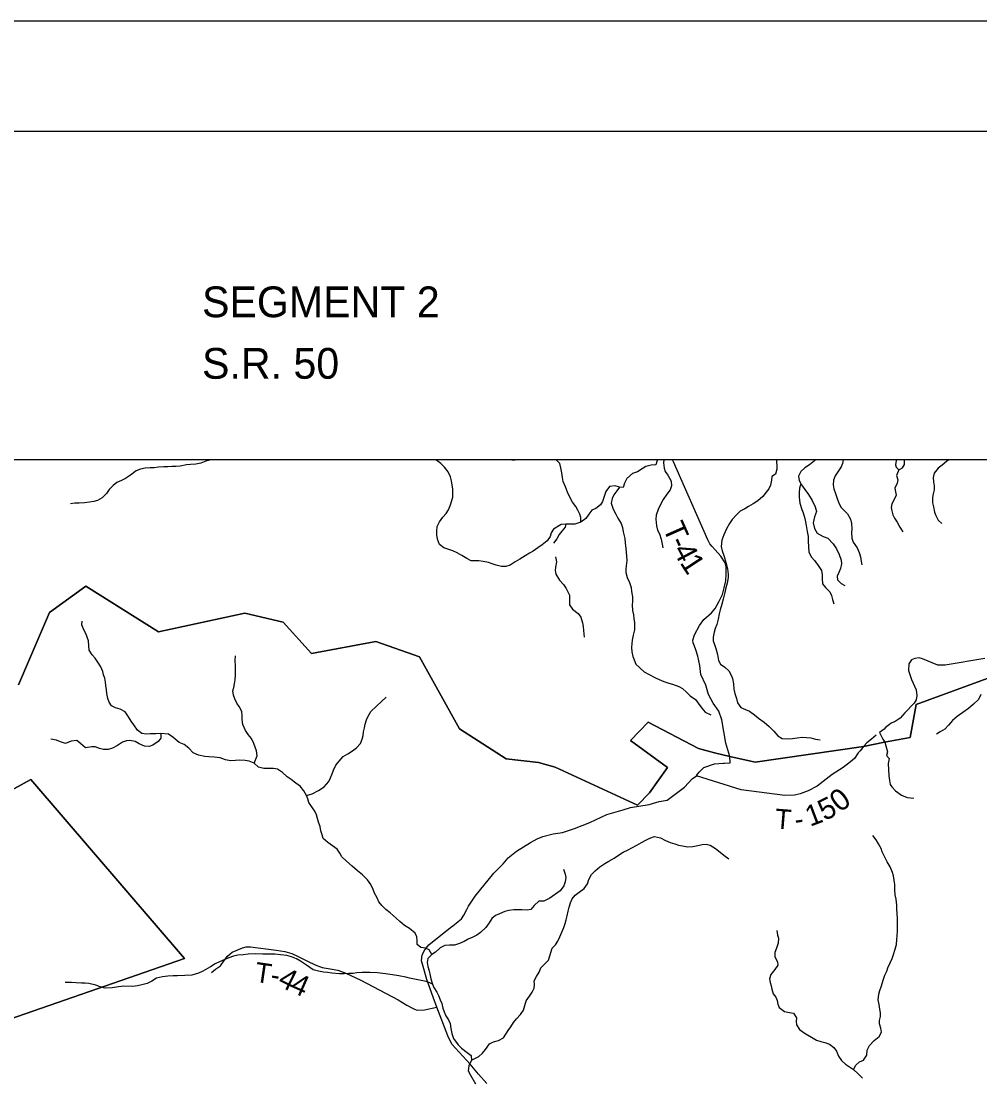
# Model space of a CAD drawing. Extents: x -139 to 835, y 0 to 440.
# Drawn here: x 462.8 to 550, y 343.7 to 440 of the extents above; entities that cross this region are included whole.
import ezdxf

# ---------------------------------------------------------------- set-up
doc = ezdxf.new("R2010")
doc.units = 0
for name, color, linetype in [('Default', 7, 'Continuous'), ('GM_X_County_Road', 7, 'Continuous'), ('GM_X_Minor_Lake', 7, 'Continuous'), ('GM_X_Minor_River', 7, 'Continuous'), ('GM_X_Township_Road', 7, 'Continuous'), ('GM_X_Township_Road_Text', 7, 'Continuous'), ('SH_Border', 7, 'Continuous'), ('SH_Cut_Line', 7, 'Continuous')]:
    doc.layers.add(name, color=color, linetype=linetype)

msp = doc.modelspace()

# ---------------------------------------------------------------- linework, layer by layer
at = {"layer": 'Default'}
for points in [[(567.097, 400.079), (373.24, 400.079)], [(462.506, 379.576), (465.334, 386.174), (468.632, 388.568), (475.272, 384.403), (483.137, 386.107), (486.604, 385.283), (489.208, 382.427), (495.052, 383.525), (499.035, 382.145), (502.665, 375.584), (506.918, 372.833), (509.868, 372.518), (511.39, 372.08), (518.877, 368.637), (519.977, 369.754), (521.593, 372.053), (518.228, 374.514), (519.84, 376.173), (524.442, 373.802), (525.876, 373.385), (527.275, 373.067), (529.599, 372.551), (539.45, 373.983), (541.372, 374.376), (543.696, 374.792), (544.238, 377.806), (556.01, 382.105)], [(556.01, 382.105), (544.238, 377.806), (543.696, 374.792), (541.372, 374.376), (539.45, 373.983), (529.599, 372.551), (527.275, 373.067), (525.876, 373.385), (524.442, 373.802), (519.84, 376.173), (518.228, 374.514), (521.593, 372.053), (519.977, 369.754), (518.877, 368.637), (511.39, 372.08), (509.868, 372.518), (506.918, 372.833), (502.665, 375.584), (499.035, 382.145), (495.052, 383.525), (489.208, 382.427), (486.604, 385.283), (483.137, 386.107), (475.272, 384.403), (468.632, 388.568), (465.334, 386.174), (462.506, 379.576)], [(458.032, 347.876), (477.617, 354.671), (463.652, 370.95), (461.283, 369.652)], [(461.283, 369.652), (463.652, 370.95), (477.617, 354.671), (458.032, 347.876)]]:
    msp.add_lwpolyline(points, dxfattribs=at)
at = {"layer": 'GM_X_County_Road'}
msp.add_lwpolyline([(507.446, 400.079), (507.578, 400.06), (507.75, 400.079)], dxfattribs=at)
at = {"layer": 'GM_X_Minor_Lake'}
msp.add_lwpolyline([(542.445, 400.079), (542.41, 400.008), (542.378, 399.601), (542.415, 399.397), (542.672, 399.166), (543.001, 399.33), (543.175, 399.639), (543.181, 400.071), (543.176, 400.079)], dxfattribs=at)
at = {"layer": 'GM_X_Minor_River'}
for points in [[(480.121, 400.079), (479.929, 400.035), (479.562, 399.929), (479.104, 399.777), (478.671, 399.672), (478.187, 399.627), (477.808, 399.606), (477.232, 399.49), (476.827, 399.444), (476.474, 399.447), (476.121, 399.437), (475.755, 399.428), (475.271, 399.395), (474.866, 399.35), (474.5, 399.329), (474.055, 399.296), (473.623, 399.227), (473.229, 399.049), (472.716, 398.669), (472.269, 398.372), (471.901, 398.17), (471.481, 397.993), (471.139, 397.732), (470.769, 397.35), (470.518, 397.004), (470.148, 396.61), (469.714, 396.373), (469.361, 396.268), (468.968, 396.211), (468.523, 396.166), (468.026, 396.133), (467.66, 396.112), (467.255, 396.067)], [(511.929, 394.164), (511.217, 393.757), (511.018, 393.41), (510.91, 393.099), (510.645, 392.692), (510.197, 392.336), (509.803, 392.062), (509.382, 391.765), (509.04, 391.563), (508.646, 391.338), (508.172, 391.029), (507.726, 390.768), (507.278, 390.483), (506.885, 390.366), (506.506, 390.369), (506.011, 390.48), (505.633, 390.591), (505.294, 390.713), (504.825, 390.824), (504.421, 390.875), (504.081, 390.866), (503.715, 390.88), (503.325, 391.075), (502.883, 391.354), (502.441, 391.585), (502.064, 391.792), (501.595, 391.927), (501.256, 392.049), (500.841, 392.364), (500.65, 392.846), (500.601, 393.23), (500.605, 393.578), (500.635, 393.998), (500.848, 394.417), (501.14, 394.835), (501.456, 395.169), (501.669, 395.503), (501.856, 395.982), (502.046, 396.653), (502.075, 396.953), (502.066, 397.433), (502.004, 397.769), (501.943, 398.142), (501.842, 398.526), (501.624, 398.96), (501.314, 399.394), (500.965, 399.745), (500.511, 400.079)], [(513.707, 394.383), (513.7, 394.815), (513.626, 395.127), (513.436, 395.477), (513.258, 395.803), (512.964, 396.215), (512.786, 396.553), (512.507, 397.12), (512.319, 397.614), (512.117, 398.108), (512.031, 398.457), (511.985, 398.877), (511.901, 399.346), (511.789, 399.719), (511.458, 400.079)], [(520.642, 400.079), (520.664, 399.995), (520.541, 399.613), (520.11, 399.594), (519.638, 399.468), (519.296, 399.256), (518.874, 398.973), (518.416, 398.835), (517.9, 398.374), (517.685, 397.933), (517.575, 397.55), (517.236, 397.566), (516.834, 397.691), (516.337, 397.637), (516.005, 397.197), (515.841, 396.72), (515.678, 396.278), (515.504, 395.968), (515.069, 395.65), (514.727, 395.474), (514.435, 395.118), (514.168, 394.737), (513.707, 394.383), (513.182, 394.197), (512.7, 394.203), (512.347, 394.195), (511.929, 394.164)], [(521.26, 400.079), (521.248, 399.796), (521.293, 399.316), (521.393, 399.015), (521.636, 398.664), (521.941, 398.133), (521.974, 397.689), (521.851, 397.342), (521.545, 396.926), (521.212, 396.463), (520.93, 395.938), (520.742, 395.533), (520.565, 395.043), (520.533, 394.66), (520.603, 394.048), (520.701, 393.651), (520.866, 393.325), (521.029, 392.855), (521.113, 392.374), (521.187, 392.05)], [(531.515, 400.079), (531.529, 399.888), (531.55, 399.564), (531.571, 399.204), (531.447, 398.773), (531.118, 398.538), (531.061, 398.215), (530.989, 397.772), (530.841, 397.438), (530.588, 397.129), (530.296, 396.737), (529.82, 396.323), (529.412, 396.052), (528.991, 395.829), (528.635, 395.605), (528.215, 395.383), (527.844, 395.027), (527.499, 394.636), (527.246, 394.267), (526.965, 393.791), (526.735, 393.242), (526.545, 392.741), (526.485, 392.19), (526.584, 391.781), (526.759, 391.263), (526.907, 390.733), (527.055, 390.144), (527.14, 389.663), (527.135, 389.351), (527.023, 388.837), (526.885, 388.287), (526.815, 387.976), (526.689, 387.39), (526.552, 386.912), (526.414, 386.41), (526.317, 386.039), (526.206, 385.573), (526.094, 385.083), (525.959, 384.713), (525.849, 384.378), (525.752, 383.936), (525.772, 383.575), (525.872, 383.262), (525.997, 382.889), (526.172, 382.347), (526.255, 381.807), (526.433, 381.469), (526.82, 381.176), (527.194, 380.86), (527.41, 380.45), (527.51, 380.149), (527.607, 379.68), (527.639, 379.188), (527.725, 378.803), (527.875, 378.345), (527.973, 377.936), (528.293, 377.525), (528.708, 377.328), (529.084, 377.179), (529.535, 376.838), (529.896, 376.546), (530.4, 376.18), (530.864, 375.779), (531.288, 375.354), (531.647, 374.954), (532.048, 374.697), (532.53, 374.679), (532.974, 374.698), (533.406, 374.753), (533.876, 374.807), (534.267, 374.802), (534.658, 374.749), (535.074, 374.648), (535.517, 374.583)], [(535.093, 400.079), (534.987, 399.966), (534.525, 399.612), (534.104, 399.329), (533.76, 398.997), (533.532, 398.568), (533.591, 398.172), (533.794, 397.786), (534.114, 397.362), (534.434, 396.915), (534.765, 396.371), (535.056, 395.792), (535.168, 395.359), (535.004, 394.869), (534.879, 394.343), (534.989, 393.826), (535.243, 393.379), (535.773, 393.073), (536.202, 392.936), (536.69, 392.426), (536.997, 391.967), (537.224, 391.46), (537.412, 390.942), (537.459, 390.606), (537.362, 390.175), (537.2, 389.817), (537.052, 389.483), (537.086, 389.147), (537.407, 388.819), (537.756, 388.611)], [(537.599, 400.079), (537.597, 400.054), (537.54, 399.731), (537.419, 399.421), (537.179, 399.076), (536.859, 398.6), (536.722, 398.206), (536.69, 397.799), (536.737, 397.438), (536.887, 396.993), (537.063, 396.535), (537.163, 396.222), (537.391, 395.763), (537.7, 395.46), (537.995, 395.145), (538.262, 394.674), (538.348, 394.277), (538.38, 393.785), (538.362, 393.461), (538.393, 392.921), (538.506, 392.56), (538.877, 392.064), (539.066, 391.642), (539.178, 391.233), (539.237, 390.812), (539.284, 390.5)], [(547.209, 400.079), (547.014, 399.905), (546.605, 399.586), (546.262, 399.302), (545.89, 398.851), (545.78, 398.456), (545.813, 398.06), (545.899, 397.711), (545.881, 397.328), (545.797, 396.957), (545.74, 396.622), (545.733, 396.166), (545.819, 395.794), (545.916, 395.313), (546.029, 394.988), (546.245, 394.565), (546.579, 394.261)], [(542.672, 399.166), (542.443, 398.653), (542.567, 398.255), (542.511, 397.932), (542.295, 397.479), (542.356, 397.155), (542.417, 396.854), (542.268, 396.508), (542.027, 396.067), (541.97, 395.732), (542.017, 395.42), (542.129, 395.059), (542.268, 394.745), (542.524, 394.382), (542.765, 393.936), (543.02, 393.525)], [(533.794, 397.786), (533.703, 397.799), (533.62, 397.488), (533.601, 397.093), (533.608, 396.673), (533.665, 396.12), (533.84, 395.555), (533.966, 395.241), (534.102, 394.724), (534.162, 394.411), (534.236, 394.099), (534.332, 393.534), (534.417, 393.101), (534.423, 392.633), (534.43, 392.19), (534.474, 391.649), (534.729, 391.202), (534.998, 390.887), (535.331, 390.452), (535.624, 390.004), (535.697, 389.596), (535.691, 389.224), (535.724, 388.792), (535.993, 388.453), (536.392, 388.052), (536.543, 387.703), (536.642, 387.354), (536.741, 386.957)], [(517.236, 397.566), (516.984, 397.257), (516.73, 396.877), (516.569, 396.531), (516.485, 396.112), (516.659, 395.582), (516.887, 395.112), (517.078, 394.75), (517.384, 394.266), (517.522, 393.893), (517.581, 393.496), (517.716, 392.907), (517.75, 392.511), (517.82, 391.994), (517.841, 391.646), (517.896, 390.914), (517.849, 390.423), (517.806, 390.1), (517.801, 389.8), (517.925, 389.355), (518.14, 388.897), (518.29, 388.439), (518.337, 388.067), (518.421, 387.586), (518.415, 387.178), (518.397, 386.855), (518.429, 386.339), (518.502, 385.954), (518.549, 385.594), (518.596, 385.257), (518.604, 384.945), (518.586, 384.586), (518.488, 384.095), (518.39, 383.641), (518.359, 383.341), (518.341, 382.982), (518.348, 382.586), (518.446, 382.165), (518.572, 381.864), (518.736, 381.466), (519.47, 380.773), (519.949, 380.516), (520.505, 380.233), (520.842, 380.061), (521.257, 379.876), (521.738, 379.739), (522.075, 379.639), (522.633, 379.44), (522.97, 379.244), (523.369, 378.891), (523.664, 378.576), (524.142, 378.258), (524.398, 377.92), (524.731, 377.472), (525.025, 377.084), (525.557, 376.85)], [(512.347, 394.195), (512.278, 393.944), (511.973, 393.576), (511.746, 393.255), (511.532, 392.886), (511.239, 392.482)], [(511.417, 391.232), (511.489, 390.788), (511.403, 390.309), (511.373, 389.998), (511.446, 389.661), (511.764, 389.118), (512.15, 388.729), (512.38, 388.367), (512.671, 387.751), (512.691, 387.367), (512.671, 386.864), (512.965, 386.465), (513.481, 386.087), (513.724, 385.736), (513.873, 385.218), (513.92, 384.894), (513.954, 384.522), (513.976, 384.222), (514.01, 383.91)], [(468.45, 384.584), (468.285, 385.041), (468.301, 385.377)], [(500.14, 355.019), (499.896, 355.465), (499.558, 355.599), (499.153, 355.674), (498.816, 355.953), (498.82, 356.289), (498.784, 356.649), (498.617, 356.962), (498.112, 357.386), (497.67, 357.677), (497.229, 358.052), (496.906, 358.354), (496.361, 358.838), (495.946, 359.141), (495.584, 359.48), (495.313, 359.842), (495.172, 360.179), (494.915, 360.612), (494.814, 360.961), (494.583, 361.419), (494.3, 361.841), (493.833, 362.276), (493.367, 362.64), (492.887, 363.075), (492.382, 363.523), (491.954, 363.91), (491.775, 364.259), (491.53, 364.609), (490.673, 365.215), (490.259, 365.59), (490.158, 365.938), (490.03, 366.299), (489.969, 366.672), (489.842, 367.081), (489.728, 367.418), (489.652, 367.742), (489.486, 368.091), (489.28, 368.393), (488.945, 368.875), (488.856, 369.2), (488.729, 369.501), (488.497, 369.922), (488.162, 370.369), (487.773, 370.636), (487.331, 370.963), (486.968, 371.193), (486.566, 371.592), (486.099, 371.907), (485.734, 371.958), (484.845, 371.964), (484.363, 372.075), (483.988, 372.462), (483.506, 372.634), (483.141, 372.708), (482.644, 372.724), (482.278, 372.702), (481.833, 372.669), (481.364, 372.768), (480.882, 372.928), (480.321, 372.992), (479.837, 373.019), (479.472, 373.058), (478.911, 373.181), (478.417, 373.389), (478.029, 373.824), (477.614, 374.151), (477.145, 374.334), (476.575, 374.83), (476.173, 375.097), (475.467, 375.162), (475.01, 375.129), (474.5, 375.108), (474.134, 375.099), (473.755, 375.138), (473.34, 375.465), (473.018, 375.935), (472.76, 376.273), (472.529, 376.658), (472.233, 377.117), (471.778, 377.372), (471.348, 377.483), (470.97, 377.677), (470.764, 377.991), (470.663, 378.328), (470.563, 378.796), (470.527, 379.121), (470.479, 379.529), (470.442, 379.829), (470.368, 380.178), (470.266, 380.503), (470.191, 380.803), (469.999, 381.213), (469.741, 381.635), (469.51, 381.996), (469.238, 382.322), (468.942, 382.744), (468.907, 383.141), (468.885, 383.585), (468.783, 383.922), (468.643, 384.247), (468.45, 384.584)], [(483.988, 372.462), (484.255, 373.108), (484.194, 373.589), (484.067, 373.914), (483.953, 374.251), (483.722, 374.696), (483.425, 375.058), (483.193, 375.432), (482.95, 375.962), (482.889, 376.43), (482.893, 376.802), (482.844, 377.163), (482.613, 377.596), (482.407, 377.922), (482.202, 378.307), (482.1, 378.644), (482.039, 379.029), (482.12, 379.352), (482.176, 379.688), (482.231, 380.036), (482.275, 380.503), (482.279, 380.887), (482.27, 381.307), (482.249, 381.812), (482.266, 382.22)], [(488.729, 369.501), (489.253, 369.653), (489.831, 369.973), (490.357, 370.306), (490.767, 370.795), (490.927, 371.13), (491.074, 371.477), (491.208, 371.824), (491.421, 372.267), (491.699, 372.649), (492.069, 373.066), (492.49, 373.315), (492.937, 373.588), (493.305, 373.85), (493.662, 374.255), (493.809, 374.626), (493.891, 374.962), (493.92, 375.298), (494.015, 375.657), (494.071, 376.005), (494.192, 376.4), (494.352, 376.723), (494.605, 377.165), (495.119, 377.63), (495.567, 378.059), (496.002, 378.464)], [(550.136, 378.712), (549.933, 378.247), (549.47, 377.808), (549.008, 377.418), (548.494, 377.065), (547.98, 376.699), (547.544, 376.333), (547.199, 375.917), (546.867, 375.537), (546.433, 375.291), (546.104, 375.079)], [(475.467, 375.162), (475.489, 374.729), (475.238, 374.419), (474.751, 374.087), (474.411, 373.969), (473.98, 373.996), (473.511, 374.215), (473.134, 374.422), (472.665, 374.509), (472.338, 374.499), (471.997, 374.358), (471.537, 374.073), (471.077, 373.824), (470.67, 373.683), (470.252, 373.698), (469.901, 373.796), (469.51, 373.931), (469.183, 373.933), (468.621, 373.853), (468.18, 374.216), (467.83, 374.519), (467.32, 374.45), (466.782, 374.25), (466.326, 374.385), (465.961, 374.544), (465.466, 374.643)], [(511.092, 355.606), (511.397, 355.926), (511.61, 356.236), (511.812, 356.653), (511.988, 357.07), (512.177, 357.488), (512.286, 357.846), (512.369, 358.193), (512.466, 358.54), (512.551, 358.982), (512.647, 359.341), (512.77, 359.735), (512.932, 360.105), (513.185, 360.45), (513.554, 360.709), (514.015, 361.028), (514.309, 361.48), (514.432, 361.874), (514.673, 362.315), (515.018, 362.658), (515.44, 363.025), (515.888, 363.331), (516.27, 363.531), (516.743, 363.789), (517.231, 364.143), (517.573, 364.342), (518.02, 364.577), (518.349, 364.741), (518.809, 364.999), (519.243, 365.234), (519.637, 365.457), (519.992, 365.632), (520.425, 365.771), (520.971, 365.669), (521.437, 365.411), (521.852, 365.238), (522.28, 365.101), (522.618, 364.977), (522.982, 364.913), (523.438, 364.847), (523.908, 364.865), (524.353, 364.956), (524.758, 365.059), (525.137, 365.079), (525.501, 364.99), (525.966, 364.673), (526.392, 364.344), (526.727, 364.076), (527.205, 363.746)], [(538.535, 344.565), (538.75, 344.97), (539.093, 345.254), (539.461, 345.417), (539.755, 345.87), (539.774, 346.325), (539.989, 346.754), (540.413, 347.193), (540.888, 347.571), (541.077, 347.964), (541.043, 348.336), (540.918, 348.71), (540.91, 349.034), (541.006, 349.38), (541.011, 349.728), (540.951, 350.052), (540.865, 350.473), (540.793, 350.894), (540.84, 351.433), (540.949, 351.755), (541.099, 352.185), (541.237, 352.711), (541.4, 353.165), (541.562, 353.511), (541.671, 353.821), (541.886, 354.263), (542.062, 354.668), (542.184, 355.038), (542.348, 355.516), (542.445, 355.935), (542.491, 356.414), (542.522, 356.713), (542.555, 357.193), (542.56, 357.552), (542.554, 357.984), (542.546, 358.368), (542.525, 358.692), (542.48, 359.208), (542.472, 359.52), (542.427, 360.06), (542.342, 360.469), (542.297, 360.937), (542.291, 361.417), (542.257, 361.801), (542.172, 362.198), (542.085, 362.511), (541.87, 363.005), (541.616, 363.476), (541.375, 363.947), (541.16, 364.381), (541.06, 364.694), (540.831, 365.105), (540.589, 365.479), (540.294, 365.867)], [(512.15, 362.789), (512.3, 362.355), (512.335, 362.055), (512.302, 361.648), (512.18, 361.29), (511.821, 360.826), (510.898, 360.166)], [(510.898, 360.166), (510.354, 359.881), (509.897, 359.884), (509.462, 359.491), (509.158, 359.145), (508.83, 359.076), (508.334, 359.091), (507.994, 359.106), (507.615, 359.096), (507.157, 359.039), (506.79, 358.934), (506.318, 358.745), (505.951, 358.592), (505.608, 358.318), (505.369, 357.912), (505.065, 357.494), (504.59, 357.041), (504.235, 356.803), (503.867, 356.614), (503.447, 356.425), (503.079, 356.223), (502.672, 356.022), (502.226, 355.881), (501.756, 355.884), (501.337, 355.851), (500.917, 355.626), (500.482, 355.245), (500.14, 355.019), (499.771, 354.662), (499.728, 354.302), (499.79, 353.93), (499.891, 353.533), (499.991, 353.112), (500.054, 352.812), (500.219, 352.33), (500.333, 352.018), (500.604, 351.62), (500.745, 351.307), (500.911, 350.921), (501.051, 350.56), (501.165, 350.151), (501.279, 349.815), (501.433, 349.465), (501.664, 349.08), (501.805, 348.767), (501.892, 348.286), (501.966, 347.854), (502.131, 347.384), (502.544, 346.817), (502.841, 346.515), (503.373, 346.128), (503.736, 345.825), (503.759, 345.417), (503.506, 344.914), (503.449, 344.459), (503.68, 344.061)], [(531.545, 357.218), (531.617, 356.809), (531.717, 356.508), (531.672, 356.053), (531.521, 355.599), (531.386, 355.229), (531.366, 354.809), (531.621, 354.363), (531.655, 354.062), (531.363, 353.682), (531.004, 353.207), (530.894, 352.812), (530.954, 352.5), (531.041, 352.187), (531.102, 351.874), (531.226, 351.465), (531.47, 351.162), (531.583, 350.849), (531.643, 350.525), (531.782, 350.211), (532.272, 349.846), (532.728, 349.756), (533.092, 349.68), (533.36, 349.281), (533.329, 348.945), (533.337, 348.633), (533.631, 348.198), (534.148, 347.832), (534.704, 347.502), (535.17, 347.244), (535.572, 347.119), (535.923, 347.031), (536.364, 346.858), (536.751, 346.565), (536.981, 346.239), (537.17, 345.781), (537.452, 345.394), (537.825, 345.053), (538.187, 344.809), (538.535, 344.565), (538.96, 344.176), (539.346, 343.764)], [(503.759, 345.417), (504.428, 345.748), (504.758, 346.058), (505.023, 346.392), (505.393, 346.894), (505.761, 347.083), (506.22, 347.212), (506.679, 347.449), (506.892, 347.783), (507.104, 348.13), (507.329, 348.452), (507.582, 348.859), (507.859, 349.181), (508.216, 349.563), (508.507, 349.957), (508.616, 350.4), (508.751, 350.831), (509.042, 351.237), (509.281, 351.607), (509.48, 351.966), (509.497, 352.302), (509.474, 352.626), (509.687, 353.033), (509.926, 353.415), (510.086, 353.834), (510.403, 354.156), (510.772, 354.514), (511.092, 355.606)], [(500.219, 352.33), (499.959, 352.464), (499.62, 352.587), (499.19, 352.674), (498.72, 352.761), (498.12, 352.873), (497.768, 352.96), (497.155, 353.084), (496.581, 353.196), (495.942, 353.284), (495.211, 353.361), (494.505, 353.39), (493.8, 353.383), (493.329, 353.362), (492.976, 353.317), (492.597, 353.295), (492.178, 353.286), (491.747, 353.289), (491.055, 353.33), (490.664, 353.393), (490.298, 353.431), (489.828, 353.507), (489.333, 353.63), (488.736, 354.054), (488.191, 354.43), (487.827, 354.625), (487.384, 354.808), (486.954, 354.931), (486.367, 355.007), (485.858, 355.058), (485.44, 355.073), (484.76, 355.078), (484.068, 355.095), (483.427, 355.075), (482.982, 355.018), (482.498, 354.962), (482.079, 354.881), (481.673, 354.727), (481.293, 354.586), (480.807, 354.373), (480.413, 354.172), (479.992, 353.923), (479.585, 353.674), (479.23, 353.484), (478.902, 353.33), (478.312, 353.142), (477.659, 353.123), (476.992, 353.104), (476.587, 353.083), (476.116, 353.05), (475.619, 352.993), (475.095, 352.877), (474.661, 352.604), (474.228, 352.403), (473.756, 352.262), (473.35, 352.181), (472.919, 352.136), (472.109, 352.141), (471.625, 352.097), (471.049, 352.005), (470.421, 351.961), (469.952, 352.084), (469.548, 352.255), (468.909, 352.392), (468.583, 352.418), (468.243, 352.42), (467.76, 352.46), (467.329, 352.487), (466.78, 352.478)], [(503.68, 344.061), (504.127, 343.252)]]:
    msp.add_lwpolyline(points, dxfattribs=at)
at = {"layer": 'GM_X_Township_Road'}
for points in [[(526.934, 390.321), (526.925, 390.439), (526.862, 390.703), (526.45, 391.305), (525.945, 391.86), (525.687, 392.162), (525.467, 392.415), (525.274, 392.788), (522.158, 399.871), (522.055, 400.063), (522.045, 400.079)], [(526.711, 372.447), (526.81, 372.454), (527.317, 372.47), (527.283, 373.051), (526.915, 374.282), (526.565, 376.383), (526.285, 377.185), (525.761, 377.907), (525.341, 378.709), (525.097, 379.543), (524.651, 380.536), (524.552, 381.352), (524.376, 382.192), (524.197, 382.757), (524.07, 383.106), (523.954, 383.406), (523.904, 383.659), (524.051, 384.125), (524.513, 384.998), (524.908, 385.535), (525.617, 386.13), (525.932, 386.524), (526.303, 387.193), (526.607, 387.803), (526.768, 388.425), (526.915, 389.036), (526.946, 389.659), (526.948, 389.933), (526.949, 390.115), (526.934, 390.321)], [(550.495, 381.979), (546.894, 381.378), (546.222, 381.366), (544.823, 381.95), (544.505, 382.049), (544.117, 381.973), (543.83, 381.858), (543.572, 381.488), (543.556, 380.895), (543.828, 380.072), (544.245, 379.132), (544.313, 378.615), (544.25, 378.224), (544.068, 377.914), (543.218, 377.041), (542.8, 376.546), (542.326, 376.247), (541.985, 376.104), (541.815, 375.986), (541.464, 375.713), (541.318, 375.554), (540.899, 375.238), (541.212, 374.647), (541.379, 374.36), (541.65, 373.497), (541.549, 373.164), (541.79, 372.884), (541.693, 372.433), (541.765, 371.287), (541.807, 370.886), (541.883, 370.496), (542.03, 370.302), (542.351, 369.922), (542.907, 369.53), (543.425, 369.312), (544.045, 369.273)], [(540.612, 375.007), (540.165, 374.647), (539.761, 374.314), (539.458, 373.967), (539.159, 373.588), (538.978, 373.382), (538.623, 372.884), (538.26, 372.574), (537.591, 372.052), (536.593, 371.424), (535.24, 370.359), (534.403, 369.945), (533.697, 369.65), (533.175, 369.533), (532.301, 369.503), (528.303, 370.032), (524.237, 371.309)], [(524.237, 371.309), (524.337, 371.448), (524.521, 371.675), (524.904, 372.069), (525.883, 372.39), (526.711, 372.447)], [(502.02, 357.626), (502.533, 358.03), (502.845, 358.295), (503.07, 358.623), (503.328, 359.117), (503.487, 359.448), (504.103, 360.35), (505.78, 362.437), (506.63, 363.294), (507.113, 363.843), (507.86, 364.456), (509.118, 365.231), (509.727, 365.573), (510.257, 365.772), (511.181, 366.024), (512.046, 366.132), (513.146, 366.511), (514.541, 367.052), (516.094, 367.773), (517.568, 368.205), (518.236, 368.422), (519.945, 368.692), (520.849, 368.963), (521.579, 369.093), (523.168, 370.279), (523.856, 371.018), (524.237, 371.309)], [(500.608, 350.252), (500.284, 351.159), (499.704, 352.767), (499.352, 353.946), (499.206, 354.456), (499.256, 354.995), (499.5, 355.466), (499.886, 355.908), (501.122, 356.918), (501.968, 357.585), (502.02, 357.626)], [(480.083, 353.404), (480.462, 353.689), (480.895, 353.998), (481.244, 354.489), (481.549, 354.886), (481.971, 355.242), (482.905, 355.651), (483.236, 355.747), (483.627, 355.72), (485.968, 355.439), (486.759, 355.301), (487.404, 355.12), (487.993, 354.845), (488.823, 354.417), (489.54, 354.09), (490.158, 353.862), (490.884, 353.738), (491.597, 353.603), (492.33, 353.347), (493.686, 352.695), (497.083, 350.92), (497.884, 350.433), (498.382, 350.162), (498.573, 350.058), (498.805, 349.977), (499.472, 349.988), (500.608, 350.252)], [(505.143, 343.285), (504.396, 344.142), (503.624, 345.036), (501.976, 346.861), (501.619, 347.625), (500.608, 350.252)]]:
    msp.add_lwpolyline(points, dxfattribs=at)
at = {"layer": 'SH_Border'}
msp.add_lwpolyline([(30, 430), (670, 430), (670, 10), (30, 10)], close=True, dxfattribs=at)
at = {"layer": 'SH_Cut_Line'}
for points in [[(0, 0), (680, 0), (680, 440), (0, 440)], [(607.596, 213.413), (607.596, 400.079), (373.24, 400.079), (373.24, 228.621), (390.412, 227.867), (402.968, 227.036), (407.389, 226.858), (433.728, 225.419), (479.461, 222.215), (494.743, 221.147), (512.652, 220.106), (533.705, 218.461), (553.865, 217.083)]]:
    msp.add_lwpolyline(points, close=True, dxfattribs=at)

# ---------------------------------------------------------------- texts
at = {"layer": 'Default'}
for s, p in [('SEGMENT 2', (479.228, 413.048)), ('S.R. 50', (479.228, 407.448))]:
    msp.add_text(s, height=2.8, dxfattribs=at).set_placement(p)
at = {"layer": 'GM_X_Township_Road_Text'}
for s, height, rotation, p in [('T', 1.976, 293.96893, (521.141, 393.892)), ('-', 1.977, 294.8143, (521.706, 392.622)), ('4', 1.98, 297.49097, (522.059, 391.864)), ('1', 1.984, 303.21387, (522.675, 390.701)), ('0', 1.963, 37.36242, (537.31, 367.909)), ('5', 1.915, 26.59712, (535.908, 367.165)), ('T', 1.802, 355.42382, (531.33, 366.523)), ('1', 1.881, 20.71783, (534.584, 366.652)), ('-', 1.811, 7.57261, (533.281, 366.419)), ('T', 1.814, 351.57851, (483.943, 352.566)), ('4', 1.914, 333.69896, (486.015, 352.26)), ('-', 1.821, 349.80477, (485.372, 352.354)), ('4', 1.9, 336.04569, (487.159, 351.697))]:
    msp.add_text(s, height=height, rotation=rotation, dxfattribs=at).set_placement(p)

doc.saveas('drawing.dxf')
